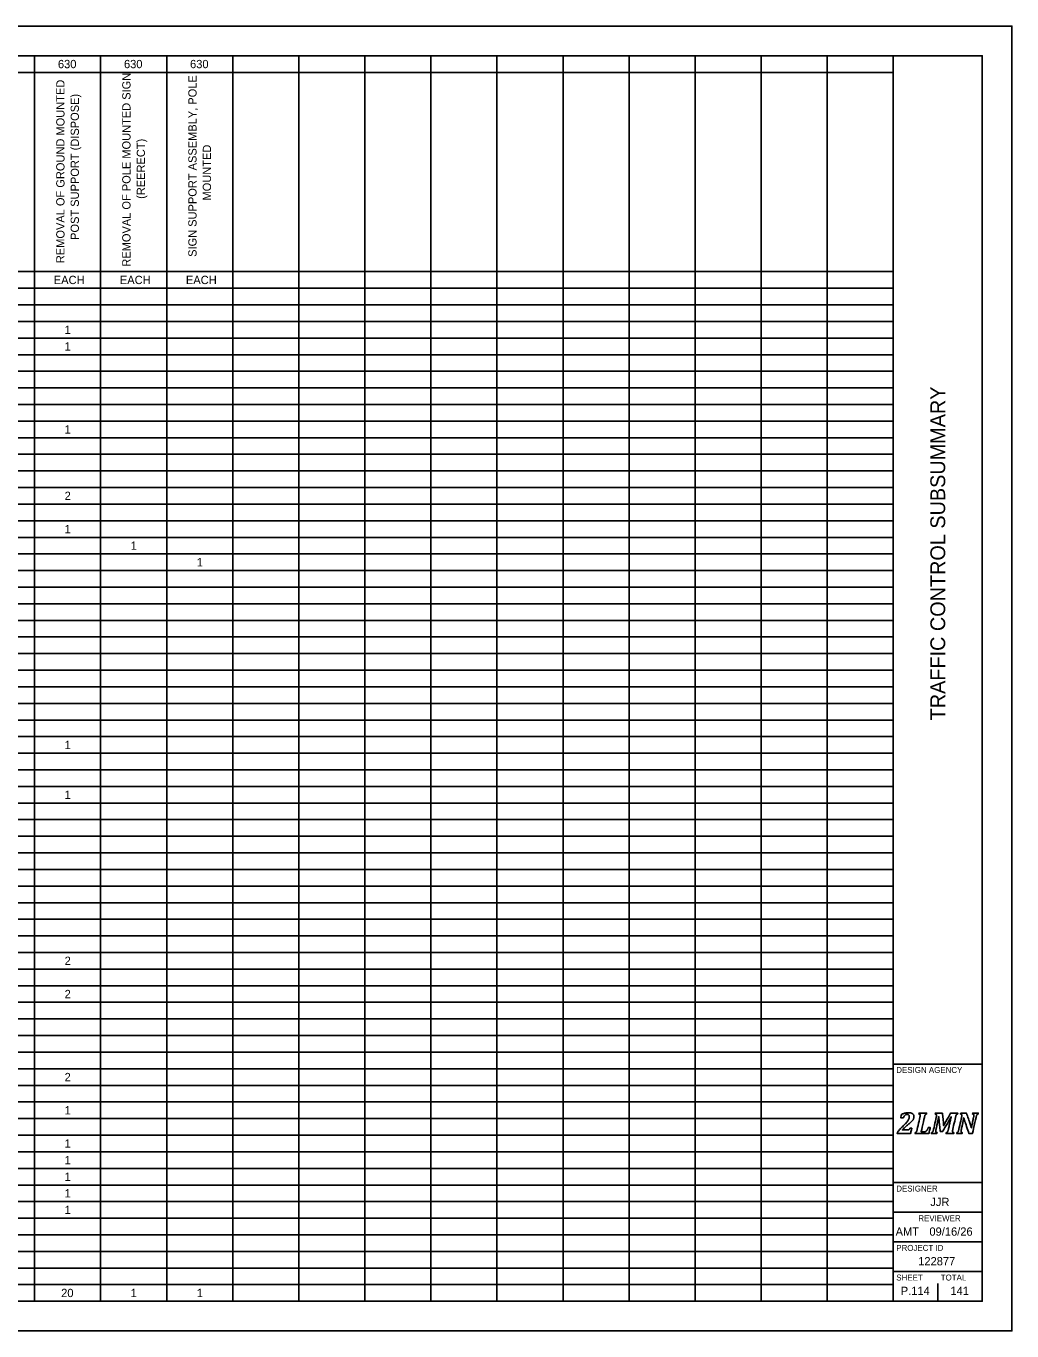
# Model space of a CAD drawing. Extents: x 0 to 34, y 0 to 22.
# Drawn here: x 17.38 to 34, y 0 to 22 of the extents above; entities that cross this region are included whole.
import ezdxf

# ---------------------------------------------------------------- set-up
doc = ezdxf.new("R2010")
doc.units = 0
for name, color, linetype in [('SH_Border', 7, 'Continuous'), ('SH_Cut_Line', 7, 'Continuous'), ('SH_Data', 7, 'Continuous'), ('SH_Text', 7, 'Continuous')]:
    doc.layers.add(name, color=color, linetype=linetype)

msp = doc.modelspace()

# ---------------------------------------------------------------- linework, layer by layer
at = {"layer": 'SH_Border'}
for p, q in [((32, 0.5), (32, 21.5)), ((32, 4.5), (33.5, 4.5)), ((32, 2.5), (33.5, 2.5)), ((32, 2), (33.5, 2)), ((32, 1.5), (33.5, 1.5)), ((32, 1), (33.5, 1))]:
    msp.add_line(p, q, dxfattribs=at)
msp.add_lwpolyline([(1.5, 21.5), (33.5, 21.5), (33.5, 0.5), (1.5, 0.5)], close=True, dxfattribs=at)
at = {"layer": 'SH_Cut_Line'}
msp.add_lwpolyline([(0, 0), (34, 0), (34, 22), (0, 22)], close=True, dxfattribs=at)
at = {"layer": 'SH_Data'}
for p, q in [((32.75, 3.5), (32.75, 3.5)), ((32.375, 0.675), (32.375, 0.675)), ((32.75, 0.5), (32.75, 0.8))]:
    msp.add_line(p, q, dxfattribs=at)
for points in [[(32.237, 3.388), (32.246, 3.388), (32.253, 3.389), (32.258, 3.39), (32.263, 3.392), (32.267, 3.394), (32.27, 3.397), (32.273, 3.401), (32.277, 3.408), (32.281, 3.417), (32.281, 3.417), (32.312, 3.417), (32.312, 3.417), (32.312, 3.417), (32.29, 3.326), (32.29, 3.326), (32.29, 3.326), (32.066, 3.326), (32.066, 3.326), (32.066, 3.326), (32.069, 3.343), (32.069, 3.343), (32.078, 3.358), (32.091, 3.375), (32.106, 3.394), (32.122, 3.412), (32.144, 3.435), (32.172, 3.462), (32.197, 3.486), (32.217, 3.506), (32.23, 3.521), (32.243, 3.537), (32.253, 3.551), (32.259, 3.566), (32.266, 3.58), (32.269, 3.595), (32.269, 3.61), (32.269, 3.622), (32.266, 3.632), (32.26, 3.64), (32.253, 3.647), (32.245, 3.65), (32.234, 3.65), (32.22, 3.65), (32.208, 3.646), (32.198, 3.636), (32.188, 3.627), (32.18, 3.613), (32.172, 3.593), (32.172, 3.593), (32.126, 3.593), (32.126, 3.593), (32.126, 3.593), (32.14, 3.654), (32.14, 3.654), (32.166, 3.663), (32.188, 3.669), (32.205, 3.673), (32.223, 3.676), (32.24, 3.678), (32.258, 3.678), (32.278, 3.678), (32.295, 3.675), (32.309, 3.669), (32.322, 3.664), (32.332, 3.656), (32.339, 3.646), (32.345, 3.637), (32.348, 3.626), (32.348, 3.613), (32.348, 3.602), (32.346, 3.591), (32.342, 3.581), (32.339, 3.571), (32.333, 3.56), (32.324, 3.549), (32.315, 3.539), (32.304, 3.526), (32.289, 3.513), (32.275, 3.499), (32.254, 3.482), (32.228, 3.46), (32.216, 3.45), (32.202, 3.438), (32.188, 3.425), (32.174, 3.412), (32.162, 3.4), (32.154, 3.391), (32.154, 3.391), (32.153, 3.388), (32.153, 3.388), (32.153, 3.388), (32.237, 3.388), (32.237, 3.388)], [(32.237, 3.388), (32.237, 3.388), (32.153, 3.388), (32.153, 3.388), (32.153, 3.388), (32.154, 3.391), (32.154, 3.391), (32.162, 3.4), (32.174, 3.412), (32.188, 3.425), (32.202, 3.438), (32.216, 3.45), (32.228, 3.46), (32.254, 3.482), (32.275, 3.499), (32.289, 3.513), (32.304, 3.526), (32.315, 3.539), (32.324, 3.549), (32.333, 3.56), (32.339, 3.571), (32.342, 3.581), (32.346, 3.591), (32.348, 3.602), (32.348, 3.613), (32.348, 3.626), (32.345, 3.637), (32.339, 3.646), (32.332, 3.656), (32.322, 3.664), (32.309, 3.669), (32.295, 3.675), (32.278, 3.678), (32.258, 3.678), (32.24, 3.678), (32.223, 3.676), (32.205, 3.673), (32.188, 3.669), (32.166, 3.663), (32.14, 3.654), (32.14, 3.654), (32.126, 3.593), (32.126, 3.593), (32.126, 3.593), (32.172, 3.593), (32.172, 3.593), (32.18, 3.613), (32.188, 3.627), (32.198, 3.636), (32.208, 3.646), (32.22, 3.65), (32.234, 3.65), (32.245, 3.65), (32.253, 3.647), (32.26, 3.64), (32.266, 3.632), (32.269, 3.622), (32.269, 3.61), (32.269, 3.595), (32.266, 3.58), (32.259, 3.566), (32.253, 3.551), (32.243, 3.537), (32.23, 3.521), (32.217, 3.506), (32.197, 3.486), (32.172, 3.462), (32.144, 3.435), (32.122, 3.412), (32.106, 3.394), (32.091, 3.375), (32.078, 3.358), (32.069, 3.343), (32.069, 3.343), (32.066, 3.326), (32.066, 3.326), (32.066, 3.326), (32.29, 3.326), (32.29, 3.326), (32.29, 3.326), (32.312, 3.417), (32.312, 3.417), (32.312, 3.417), (32.281, 3.417), (32.281, 3.417), (32.277, 3.408), (32.273, 3.401), (32.27, 3.397), (32.267, 3.394), (32.263, 3.392), (32.258, 3.39), (32.253, 3.389), (32.246, 3.388), (32.237, 3.388)], [(32.518, 3.356), (32.527, 3.356), (32.533, 3.357), (32.538, 3.358), (32.542, 3.36), (32.546, 3.362), (32.55, 3.365), (32.554, 3.368), (32.558, 3.372), (32.562, 3.377), (32.567, 3.382), (32.571, 3.388), (32.576, 3.397), (32.58, 3.405), (32.585, 3.415), (32.589, 3.427), (32.589, 3.427), (32.624, 3.427), (32.624, 3.427), (32.624, 3.427), (32.598, 3.326), (32.598, 3.326), (32.598, 3.326), (32.365, 3.326), (32.365, 3.326), (32.365, 3.326), (32.369, 3.343), (32.369, 3.343), (32.376, 3.345), (32.381, 3.348), (32.385, 3.351), (32.389, 3.355), (32.392, 3.36), (32.395, 3.366), (32.398, 3.373), (32.4, 3.382), (32.403, 3.395), (32.403, 3.395), (32.449, 3.605), (32.449, 3.605), (32.452, 3.615), (32.453, 3.625), (32.453, 3.635), (32.453, 3.642), (32.451, 3.647), (32.448, 3.651), (32.444, 3.654), (32.439, 3.656), (32.432, 3.657), (32.432, 3.657), (32.435, 3.674), (32.435, 3.674), (32.435, 3.674), (32.563, 3.674), (32.563, 3.674), (32.563, 3.674), (32.559, 3.657), (32.559, 3.657), (32.552, 3.655), (32.547, 3.652), (32.543, 3.649), (32.539, 3.645), (32.536, 3.64), (32.533, 3.634), (32.531, 3.627), (32.528, 3.618), (32.525, 3.605), (32.525, 3.605), (32.47, 3.356), (32.47, 3.356), (32.47, 3.356), (32.518, 3.356), (32.518, 3.356)], [(32.518, 3.356), (32.518, 3.356), (32.47, 3.356), (32.47, 3.356), (32.47, 3.356), (32.525, 3.605), (32.525, 3.605), (32.528, 3.618), (32.531, 3.627), (32.533, 3.634), (32.536, 3.64), (32.539, 3.645), (32.543, 3.649), (32.547, 3.652), (32.552, 3.655), (32.559, 3.657), (32.559, 3.657), (32.563, 3.674), (32.563, 3.674), (32.563, 3.674), (32.435, 3.674), (32.435, 3.674), (32.435, 3.674), (32.432, 3.657), (32.432, 3.657), (32.439, 3.656), (32.444, 3.654), (32.448, 3.651), (32.451, 3.647), (32.453, 3.642), (32.453, 3.635), (32.453, 3.625), (32.452, 3.615), (32.449, 3.605), (32.449, 3.605), (32.403, 3.395), (32.403, 3.395), (32.4, 3.382), (32.398, 3.373), (32.395, 3.366), (32.392, 3.36), (32.389, 3.355), (32.385, 3.351), (32.381, 3.348), (32.376, 3.345), (32.369, 3.343), (32.369, 3.343), (32.365, 3.326), (32.365, 3.326), (32.365, 3.326), (32.598, 3.326), (32.598, 3.326), (32.598, 3.326), (32.624, 3.427), (32.624, 3.427), (32.624, 3.427), (32.589, 3.427), (32.589, 3.427), (32.585, 3.415), (32.58, 3.405), (32.576, 3.397), (32.571, 3.388), (32.567, 3.382), (32.562, 3.377), (32.558, 3.372), (32.554, 3.368), (32.55, 3.365), (32.546, 3.362), (32.542, 3.36), (32.538, 3.358), (32.533, 3.357), (32.527, 3.356), (32.518, 3.356)], [(32.829, 3.674), (32.829, 3.674), (32.849, 3.461), (32.849, 3.461), (32.849, 3.461), (32.969, 3.674), (32.969, 3.674), (32.969, 3.674), (33.087, 3.674), (33.087, 3.674), (33.087, 3.674), (33.084, 3.657), (33.084, 3.657), (33.077, 3.655), (33.071, 3.652), (33.067, 3.649), (33.064, 3.645), (33.06, 3.64), (33.058, 3.634), (33.055, 3.627), (33.052, 3.618), (33.05, 3.605), (33.05, 3.605), (33.003, 3.395), (33.003, 3.395), (33.002, 3.39), (33.002, 3.387), (33.001, 3.384), (33.001, 3.382), (33.001, 3.379), (33, 3.376), (33, 3.373), (33, 3.369), (33, 3.365), (33, 3.358), (33.002, 3.353), (33.005, 3.349), (33.008, 3.346), (33.014, 3.344), (33.021, 3.343), (33.021, 3.343), (33.018, 3.326), (33.018, 3.326), (33.018, 3.326), (32.89, 3.326), (32.89, 3.326), (32.89, 3.326), (32.893, 3.343), (32.893, 3.343), (32.9, 3.345), (32.906, 3.348), (32.91, 3.351), (32.914, 3.355), (32.917, 3.36), (32.919, 3.366), (32.922, 3.373), (32.925, 3.382), (32.928, 3.395), (32.928, 3.395), (32.951, 3.502), (32.951, 3.502), (32.954, 3.513), (32.957, 3.529), (32.962, 3.548), (32.967, 3.568), (32.972, 3.588), (32.978, 3.609), (32.978, 3.609), (32.973, 3.609), (32.973, 3.609), (32.965, 3.594), (32.957, 3.579), (32.948, 3.563), (32.948, 3.563), (32.833, 3.364), (32.833, 3.364), (32.833, 3.364), (32.792, 3.364), (32.792, 3.364), (32.792, 3.364), (32.775, 3.518), (32.775, 3.518), (32.773, 3.537), (32.772, 3.554), (32.77, 3.569), (32.769, 3.583), (32.768, 3.597), (32.768, 3.611), (32.768, 3.611), (32.764, 3.611), (32.764, 3.611), (32.761, 3.596), (32.758, 3.578), (32.755, 3.558), (32.751, 3.538), (32.747, 3.521), (32.744, 3.507), (32.744, 3.507), (32.72, 3.395), (32.72, 3.395), (32.719, 3.39), (32.718, 3.387), (32.718, 3.384), (32.717, 3.382), (32.717, 3.379), (32.717, 3.376), (32.717, 3.373), (32.716, 3.369), (32.716, 3.365), (32.716, 3.358), (32.718, 3.353), (32.721, 3.349), (32.725, 3.346), (32.73, 3.344), (32.738, 3.343), (32.738, 3.343), (32.734, 3.326), (32.734, 3.326), (32.734, 3.326), (32.641, 3.326), (32.641, 3.326), (32.641, 3.326), (32.644, 3.343), (32.644, 3.343), (32.651, 3.345), (32.657, 3.348), (32.661, 3.351), (32.665, 3.355), (32.668, 3.36), (32.67, 3.366), (32.673, 3.373), (32.676, 3.382), (32.679, 3.395), (32.679, 3.395), (32.725, 3.605), (32.725, 3.605), (32.727, 3.615), (32.728, 3.625), (32.728, 3.635), (32.728, 3.642), (32.727, 3.647), (32.723, 3.651), (32.72, 3.654), (32.715, 3.656), (32.707, 3.657), (32.707, 3.657), (32.711, 3.674), (32.711, 3.674), (32.711, 3.674), (32.829, 3.674), (32.829, 3.674)], [(32.829, 3.674), (32.829, 3.674), (32.711, 3.674), (32.711, 3.674), (32.711, 3.674), (32.707, 3.657), (32.707, 3.657), (32.715, 3.656), (32.72, 3.654), (32.723, 3.651), (32.727, 3.647), (32.728, 3.642), (32.728, 3.635), (32.728, 3.625), (32.727, 3.615), (32.725, 3.605), (32.725, 3.605), (32.679, 3.395), (32.679, 3.395), (32.676, 3.382), (32.673, 3.373), (32.67, 3.366), (32.668, 3.36), (32.665, 3.355), (32.661, 3.351), (32.657, 3.348), (32.651, 3.345), (32.644, 3.343), (32.644, 3.343), (32.641, 3.326), (32.641, 3.326), (32.641, 3.326), (32.734, 3.326), (32.734, 3.326), (32.734, 3.326), (32.738, 3.343), (32.738, 3.343), (32.73, 3.344), (32.725, 3.346), (32.721, 3.349), (32.718, 3.353), (32.716, 3.358), (32.716, 3.365), (32.716, 3.369), (32.717, 3.373), (32.717, 3.376), (32.717, 3.379), (32.717, 3.382), (32.718, 3.384), (32.718, 3.387), (32.719, 3.39), (32.72, 3.395), (32.72, 3.395), (32.744, 3.507), (32.744, 3.507), (32.747, 3.521), (32.751, 3.538), (32.755, 3.558), (32.758, 3.578), (32.761, 3.596), (32.764, 3.611), (32.764, 3.611), (32.768, 3.611), (32.768, 3.611), (32.768, 3.597), (32.769, 3.583), (32.77, 3.569), (32.772, 3.554), (32.773, 3.537), (32.775, 3.518), (32.775, 3.518), (32.792, 3.364), (32.792, 3.364), (32.792, 3.364), (32.833, 3.364), (32.833, 3.364), (32.833, 3.364), (32.948, 3.563), (32.948, 3.563), (32.957, 3.579), (32.965, 3.594), (32.973, 3.609), (32.973, 3.609), (32.978, 3.609), (32.978, 3.609), (32.972, 3.588), (32.967, 3.568), (32.962, 3.548), (32.957, 3.529), (32.954, 3.513), (32.951, 3.502), (32.951, 3.502), (32.928, 3.395), (32.928, 3.395), (32.925, 3.382), (32.922, 3.373), (32.919, 3.366), (32.917, 3.36), (32.914, 3.355), (32.91, 3.351), (32.906, 3.348), (32.9, 3.345), (32.893, 3.343), (32.893, 3.343), (32.89, 3.326), (32.89, 3.326), (32.89, 3.326), (33.018, 3.326), (33.018, 3.326), (33.018, 3.326), (33.021, 3.343), (33.021, 3.343), (33.014, 3.344), (33.008, 3.346), (33.005, 3.349), (33.002, 3.353), (33, 3.358), (33, 3.365), (33, 3.369), (33, 3.373), (33, 3.376), (33.001, 3.379), (33.001, 3.382), (33.001, 3.384), (33.002, 3.387), (33.002, 3.39), (33.003, 3.395), (33.003, 3.395), (33.05, 3.605), (33.05, 3.605), (33.052, 3.618), (33.055, 3.627), (33.058, 3.634), (33.06, 3.64), (33.064, 3.645), (33.067, 3.649), (33.071, 3.652), (33.077, 3.655), (33.084, 3.657), (33.084, 3.657), (33.087, 3.674), (33.087, 3.674), (33.087, 3.674), (32.969, 3.674), (32.969, 3.674), (32.969, 3.674), (32.849, 3.461), (32.849, 3.461), (32.849, 3.461), (32.829, 3.674), (32.829, 3.674)], [(33.137, 3.674), (33.137, 3.674), (33.234, 3.674), (33.234, 3.674), (33.234, 3.674), (33.283, 3.53), (33.283, 3.53), (33.296, 3.49), (33.307, 3.456), (33.315, 3.426), (33.315, 3.426), (33.318, 3.426), (33.318, 3.426), (33.323, 3.455), (33.329, 3.488), (33.337, 3.523), (33.337, 3.523), (33.355, 3.605), (33.355, 3.605), (33.357, 3.615), (33.358, 3.625), (33.358, 3.635), (33.358, 3.642), (33.357, 3.647), (33.353, 3.651), (33.35, 3.654), (33.345, 3.656), (33.337, 3.657), (33.337, 3.657), (33.341, 3.674), (33.341, 3.674), (33.341, 3.674), (33.434, 3.674), (33.434, 3.674), (33.434, 3.674), (33.431, 3.657), (33.431, 3.657), (33.424, 3.655), (33.418, 3.652), (33.414, 3.649), (33.41, 3.645), (33.407, 3.64), (33.405, 3.634), (33.402, 3.627), (33.399, 3.618), (33.396, 3.605), (33.396, 3.605), (33.335, 3.326), (33.335, 3.326), (33.335, 3.326), (33.277, 3.326), (33.277, 3.326), (33.277, 3.326), (33.216, 3.504), (33.216, 3.504), (33.211, 3.518), (33.207, 3.531), (33.204, 3.543), (33.2, 3.556), (33.195, 3.571), (33.19, 3.59), (33.19, 3.59), (33.186, 3.59), (33.186, 3.59), (33.185, 3.579), (33.182, 3.563), (33.179, 3.543), (33.175, 3.523), (33.17, 3.501), (33.165, 3.478), (33.165, 3.478), (33.147, 3.395), (33.147, 3.395), (33.146, 3.39), (33.145, 3.387), (33.145, 3.384), (33.144, 3.382), (33.144, 3.379), (33.144, 3.376), (33.143, 3.373), (33.143, 3.369), (33.143, 3.365), (33.143, 3.358), (33.145, 3.353), (33.148, 3.349), (33.152, 3.346), (33.157, 3.344), (33.164, 3.343), (33.164, 3.343), (33.161, 3.326), (33.161, 3.326), (33.161, 3.326), (33.067, 3.326), (33.067, 3.326), (33.067, 3.326), (33.071, 3.343), (33.071, 3.343), (33.078, 3.345), (33.083, 3.348), (33.087, 3.351), (33.091, 3.355), (33.094, 3.36), (33.097, 3.366), (33.1, 3.373), (33.102, 3.382), (33.105, 3.395), (33.105, 3.395), (33.151, 3.605), (33.151, 3.605), (33.154, 3.615), (33.155, 3.625), (33.155, 3.635), (33.155, 3.642), (33.153, 3.647), (33.15, 3.651), (33.146, 3.654), (33.141, 3.656), (33.134, 3.657), (33.134, 3.657), (33.137, 3.674), (33.137, 3.674)], [(33.137, 3.674), (33.137, 3.674), (33.134, 3.657), (33.134, 3.657), (33.141, 3.656), (33.146, 3.654), (33.15, 3.651), (33.153, 3.647), (33.155, 3.642), (33.155, 3.635), (33.155, 3.625), (33.154, 3.615), (33.151, 3.605), (33.151, 3.605), (33.105, 3.395), (33.105, 3.395), (33.102, 3.382), (33.1, 3.373), (33.097, 3.366), (33.094, 3.36), (33.091, 3.355), (33.087, 3.351), (33.083, 3.348), (33.078, 3.345), (33.071, 3.343), (33.071, 3.343), (33.067, 3.326), (33.067, 3.326), (33.067, 3.326), (33.161, 3.326), (33.161, 3.326), (33.161, 3.326), (33.164, 3.343), (33.164, 3.343), (33.157, 3.344), (33.152, 3.346), (33.148, 3.349), (33.145, 3.353), (33.143, 3.358), (33.143, 3.365), (33.143, 3.369), (33.143, 3.373), (33.144, 3.376), (33.144, 3.379), (33.144, 3.382), (33.145, 3.384), (33.145, 3.387), (33.146, 3.39), (33.147, 3.395), (33.147, 3.395), (33.165, 3.478), (33.165, 3.478), (33.17, 3.501), (33.175, 3.523), (33.179, 3.543), (33.182, 3.563), (33.185, 3.579), (33.186, 3.59), (33.186, 3.59), (33.19, 3.59), (33.19, 3.59), (33.195, 3.571), (33.2, 3.556), (33.204, 3.543), (33.207, 3.531), (33.211, 3.518), (33.216, 3.504), (33.216, 3.504), (33.277, 3.326), (33.277, 3.326), (33.277, 3.326), (33.335, 3.326), (33.335, 3.326), (33.335, 3.326), (33.396, 3.605), (33.396, 3.605), (33.399, 3.618), (33.402, 3.627), (33.405, 3.634), (33.407, 3.64), (33.41, 3.645), (33.414, 3.649), (33.418, 3.652), (33.424, 3.655), (33.431, 3.657), (33.431, 3.657), (33.434, 3.674), (33.434, 3.674), (33.434, 3.674), (33.341, 3.674), (33.341, 3.674), (33.341, 3.674), (33.337, 3.657), (33.337, 3.657), (33.345, 3.656), (33.35, 3.654), (33.353, 3.651), (33.357, 3.647), (33.358, 3.642), (33.358, 3.635), (33.358, 3.625), (33.357, 3.615), (33.355, 3.605), (33.355, 3.605), (33.337, 3.523), (33.337, 3.523), (33.329, 3.488), (33.323, 3.455), (33.318, 3.426), (33.318, 3.426), (33.315, 3.426), (33.315, 3.426), (33.307, 3.456), (33.296, 3.49), (33.283, 3.53), (33.283, 3.53), (33.234, 3.674), (33.234, 3.674), (33.234, 3.674), (33.137, 3.674), (33.137, 3.674)]]:
    msp.add_open_spline(points, degree=3, dxfattribs=at)
at = {"layer": 'SH_Text'}
for p, q in [((1.5, 21.5), (32, 21.5)), ((17.52, 21.5), (17.52, 0.5)), ((18.634, 21.5), (18.634, 0.5)), ((19.748, 21.5), (19.748, 0.5)), ((20.861, 21.5), (20.861, 0.5)), ((21.975, 21.5), (21.975, 0.5)), ((23.089, 21.5), (23.089, 0.5)), ((24.203, 21.5), (24.203, 0.5)), ((25.317, 21.5), (25.317, 0.5)), ((26.431, 21.5), (26.431, 0.5)), ((27.545, 21.5), (27.545, 0.5)), ((28.658, 21.5), (28.658, 0.5)), ((29.772, 21.5), (29.772, 0.5)), ((30.886, 21.5), (30.886, 0.5)), ((32, 21.5), (32, 0.5)), ((10.673, 21.22), (32, 21.22)), ((10.673, 17.86), (32, 17.86)), ((1.5, 17.58), (32, 17.58)), ((1.5, 17.3), (32, 17.3)), ((1.5, 17.02), (32, 17.02)), ((1.5, 16.74), (32, 16.74)), ((1.5, 16.46), (32, 16.46)), ((1.5, 16.18), (32, 16.18)), ((1.5, 15.9), (32, 15.9)), ((1.5, 15.62), (32, 15.62)), ((1.5, 15.34), (32, 15.34)), ((1.5, 15.06), (32, 15.06)), ((1.5, 14.78), (32, 14.78)), ((1.5, 14.5), (32, 14.5)), ((1.5, 14.22), (32, 14.22)), ((1.5, 13.94), (32, 13.94)), ((1.5, 13.66), (32, 13.66)), ((1.5, 13.38), (32, 13.38)), ((1.5, 13.1), (32, 13.1)), ((1.5, 12.82), (32, 12.82)), ((1.5, 12.54), (32, 12.54)), ((1.5, 12.26), (32, 12.26)), ((1.5, 11.98), (32, 11.98)), ((1.5, 11.7), (32, 11.7)), ((1.5, 11.42), (32, 11.42)), ((1.5, 11.14), (32, 11.14)), ((1.5, 10.86), (32, 10.86)), ((1.5, 10.58), (32, 10.58)), ((1.5, 10.3), (32, 10.3)), ((1.5, 10.02), (32, 10.02)), ((1.5, 9.74), (32, 9.74)), ((1.5, 9.46), (32, 9.46)), ((1.5, 9.18), (32, 9.18)), ((1.5, 8.9), (32, 8.9)), ((1.5, 8.62), (32, 8.62)), ((1.5, 8.34), (32, 8.34)), ((1.5, 8.06), (32, 8.06)), ((1.5, 7.78), (32, 7.78)), ((1.5, 7.5), (32, 7.5)), ((1.5, 7.22), (32, 7.22)), ((1.5, 6.94), (32, 6.94)), ((1.5, 6.66), (32, 6.66)), ((1.5, 6.38), (32, 6.38)), ((1.5, 6.1), (32, 6.1)), ((1.5, 5.82), (32, 5.82)), ((1.5, 5.54), (32, 5.54)), ((1.5, 5.26), (32, 5.26)), ((1.5, 4.98), (32, 4.98)), ((1.5, 4.7), (32, 4.7)), ((1.5, 4.42), (32, 4.42)), ((1.5, 4.14), (32, 4.14)), ((1.5, 3.86), (32, 3.86)), ((1.5, 3.58), (32, 3.58)), ((1.5, 3.3), (32, 3.3)), ((1.5, 3.02), (32, 3.02)), ((1.5, 2.74), (32, 2.74)), ((1.5, 2.46), (32, 2.46)), ((1.5, 2.18), (32, 2.18)), ((1.5, 1.9), (32, 1.9)), ((1.5, 1.62), (32, 1.62)), ((1.5, 1.34), (32, 1.34)), ((1.5, 1.06), (32, 1.06)), ((1.5, 0.78), (32, 0.78)), ((1.5, 0.5), (32, 0.5))]:
    msp.add_line(p, q, dxfattribs=at)

# ---------------------------------------------------------------- texts
at = {"layer": 'SH_Data'}
msp.add_text('TRAFFIC CONTROL SUBSUMMARY', height=0.25, rotation=90, dxfattribs=at).set_placement((32.875, 10.295))
for s, height, p in [('DESIGN AGENCY', 0.1, (32.05, 4.35)), ('DESIGNER', 0.1, (32.05, 2.35)), ('JJR', 0.14, (32.624, 2.105)), ('REVIEWER', 0.1, (32.422, 1.85)), ('AMT', 0.14, (32.039, 1.605)), ('09/16/26', 0.14, (32.609, 1.605)), ('PROJECT ID', 0.1, (32.05, 1.35)), ('122877', 0.14, (32.42, 1.105)), ('SHEET', 0.1, (32.05, 0.85)), ('TOTAL', 0.1, (32.8, 0.85)), ('P.114', 0.14, (32.126, 0.605)), ('141', 0.14, (32.963, 0.605))]:
    msp.add_text(s, height=height, dxfattribs=at).set_placement(p)
at = {"layer": 'SH_Text'}
for s, p in [('630', (17.914, 21.29)), ('630', (19.028, 21.29)), ('630', (20.142, 21.29)), ('EACH', (17.844, 17.65)), ('EACH', (18.958, 17.65)), ('EACH', (20.072, 17.65)), ('1', (18.027, 16.81)), ('1', (18.027, 16.53)), ('1', (18.027, 15.13)), ('2', (18.027, 14.01)), ('1', (18.027, 13.45)), ('1', (19.141, 13.17)), ('1', (20.255, 12.89)), ('1', (18.027, 9.81)), ('1', (18.027, 8.97)), ('2', (18.027, 6.17)), ('2', (18.027, 5.61)), ('2', (18.027, 4.21)), ('1', (18.027, 3.65)), ('1', (18.027, 3.09)), ('1', (18.027, 2.81)), ('1', (18.027, 2.53)), ('1', (18.027, 2.25)), ('1', (18.027, 1.97)), ('20', (17.969, 0.57)), ('1', (19.14, 0.57)), ('1', (20.255, 0.57))]:
    msp.add_text(s, height=0.14, dxfattribs=at).set_placement(p)
for s, height, p in [('REMOVAL OF POLE MOUNTED SIGN ', 0.13923, (19.138, 17.944)), ('SIGN SUPPORT ASSEMBLY, POLE ', 0.13923, (20.252, 18.109)), ('REMOVAL OF GROUND MOUNTED ', 0.13923, (18.025, 18.003)), ('POST SUPPORT (DISPOSE)', 0.13923, (18.268, 18.395)), ('(REERECT)', 0.1392, (19.382, 19.087)), ('MOUNTED', 0.1392, (20.496, 19.06))]:
    msp.add_text(s, height=height, rotation=90, dxfattribs=at).set_placement(p)

doc.saveas('drawing.dxf')
